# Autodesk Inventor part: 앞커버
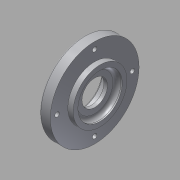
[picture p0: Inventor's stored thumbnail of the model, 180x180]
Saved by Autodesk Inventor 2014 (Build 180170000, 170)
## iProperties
Created: 2015-09
Part Number: 앞커버
Material: 알루미늄 6061
Document SubType Name: Modeling
Designer: mduedu
Density: 2.71 g/cm^3
Appearance: 알루미늄 - 평지
Mass: 71.1437 g
Surface Area: 102.916 cm^2
Volume: 26.2523 cm^3
Author: mduedu
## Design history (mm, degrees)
sketch "스케치1"
  geometry: L1 (-8, 67)-(-12, 67); L2 (-12, 67)-(-12, 80); L3 (-12, 80)-(-20, 80); L4 (-20, 80)-(-20, 70.5); L5 (-23, 70.5)-(-23, 56.5); L6 (-23, 56.5)-(-8, 56.5); L7 (-8, 56.5)-(-8, 67); L8 (-79.5, 39.5)-(-79.5, 54.5) reference; L9 (48.5, 54.5)-(48.5, 39.5) reference; L10 (-79.5, 47)-(48.5, 47); L11 (-20, 70.5)-(-23, 70.5); 3 further points
  constraints: 18 end point, 6 parallel, 4 midpoint, 1 horizontal, 1 perpendicular, 1 vertical alignment
  dimensions: "d0" = 15 distance between parallel lines of L7 L5; "d2" = 19 diameter of L6 L10; "d3" = 40 diameter of L1 L10; "d5" = 4 distance of L1.start L1.end; "d6" = 66 diameter of L3 L10; "d7" = 8 distance of L2.end L3.end; "d8" = 47 diameter of L4.end L10
revolve "회전1" sketch "스케치1" stored, may be unused: angle "d4" = 90 deg
sketch "스케치2"
  geometry: C1 r 33 at (0, 0) reference; 2 further points
  constraints: 1 coincident
hole "구멍1" sketch "스케치2" at (0, 0) diameter "d11" = 33; stored, may be unused: countersink angle "d15" = 90 deg, drill point angle "d17" = 0 deg; dims "d12" = 6, "d13" = 4, "d14" = 2, "d16" = 4
fillet "모깎기1" dims "d18" = 3
fillet "모깎기2" dims "d19" = 1
sketch "스케치3"
  geometry: C1 r 33 at (0, 0) reference; 2 further points
  constraints: 1 coincident
hole "구멍2" sketch "스케치3" at (0, 0) diameter "d20" = 32; stored, may be unused: countersink angle "d24" = 90 deg, drill point angle "d26" = 0 deg; dims "d21" = 6, "d22" = 4, "d23" = 2, "d25" = 8.3
fillet "모깎기3" dims "d27" = 0.3
chamfer "모따기1" distance "d28" = 0.8; stored, may be unused: second distance "d29" = 2, angle "d30" = 30 deg
sketch "스케치4" dims "d31" = 56
  geometry: C1 r 33 at (0, 0) reference; 6 further points
  constraints: 2 vertical alignment, 1 coincident, 7 other
  dimensions: "d36" = 360 deg dimension on C1.centre point (0, 28) (derived)
sketch "스케치7"
  geometry: 4 further points
hole "구멍4" sketch "스케치7" at (0, 28), (-28, 0), (28, 0), (0, -28) diameter "d48" = 3.4; stored, may be unused: countersink angle "d52" = 90 deg, drill point angle "d54" = 0 deg; dims "d49" = 6, "d50" = 6.5, "d51" = 3.4, "d53" = 8
node "솔리드1"
node "참조1"
node "참조2"
